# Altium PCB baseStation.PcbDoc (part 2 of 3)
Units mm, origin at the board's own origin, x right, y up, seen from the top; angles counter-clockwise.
Board outline 130 x 90 mm, 4 copper layers (Top Layer, Ground Layer, Power Layer, Bottom Layer), stack 1.574 mm thick; 252 components, 154 nets, 772 pads, 1223 vias.
Unrouted connection lines stored in the file: 134.
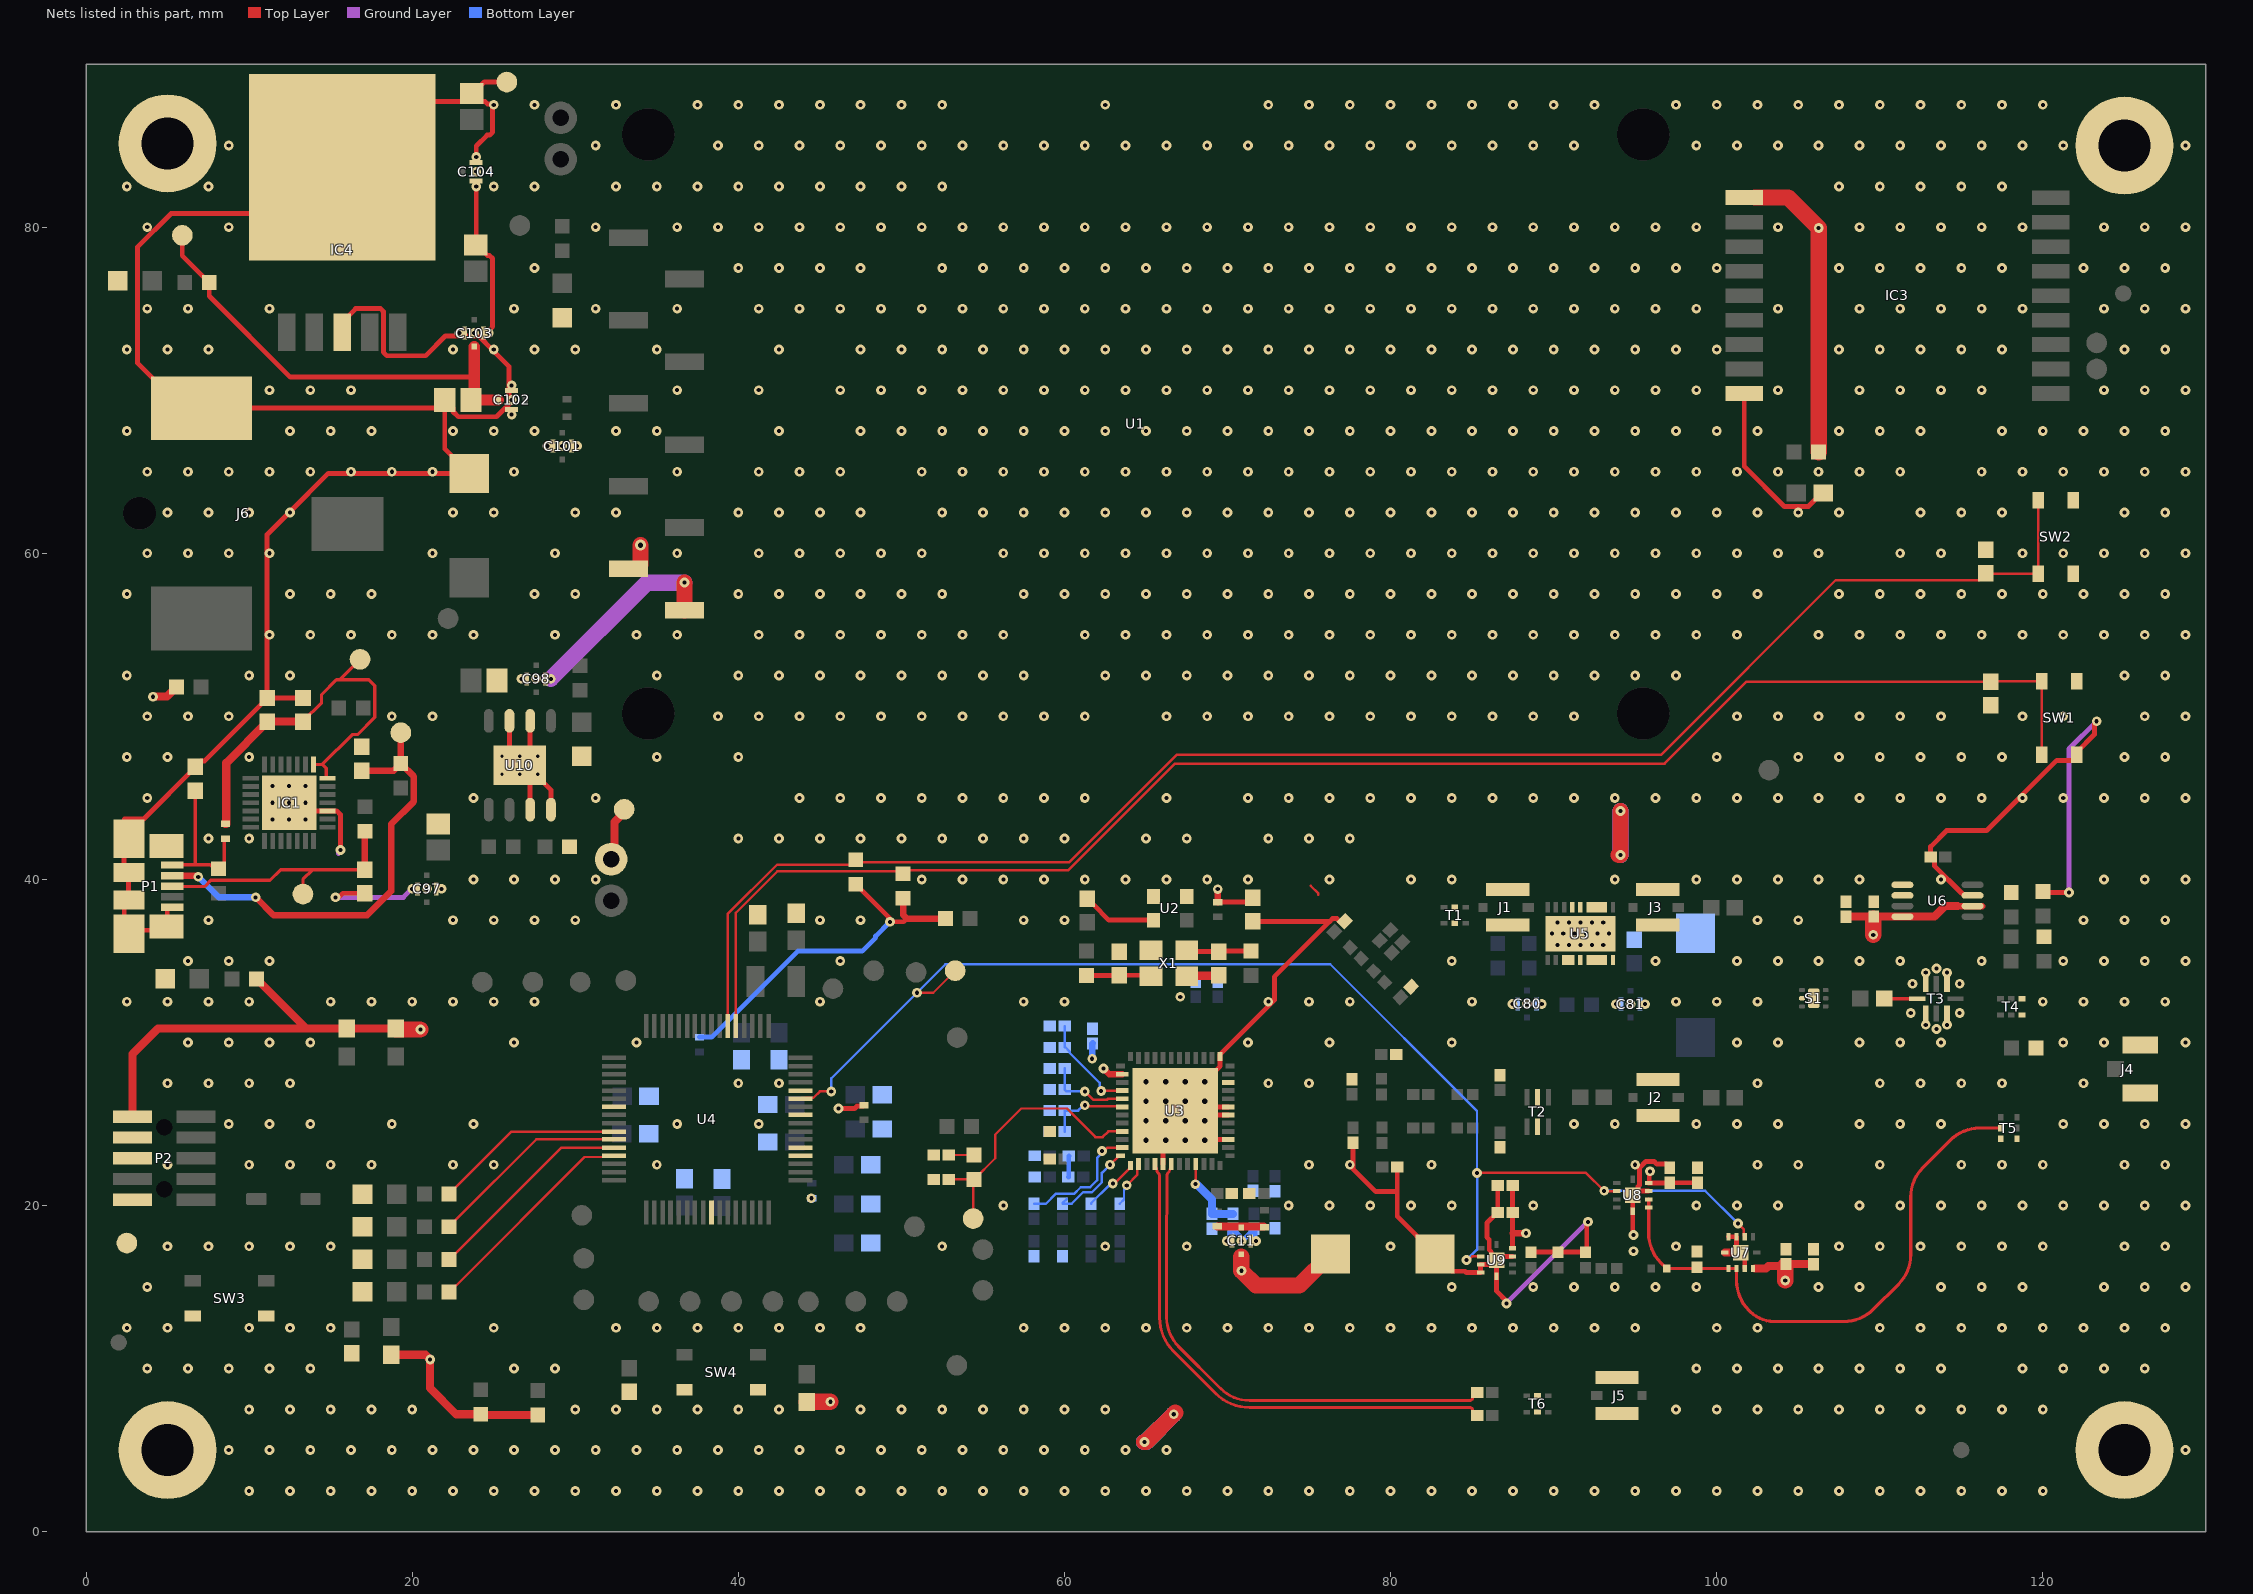
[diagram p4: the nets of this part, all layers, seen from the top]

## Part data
C1 C2 C3 C4 C5 C6 C7 C62 C63 C64 C65 C66 C67 C68 C69 C70 C71 C72 C73 C74 C75 C78 C79: "Capacitor"
C8 C9 C10 C12 C13 C14 C18 C43 C47 C49 C58 C60: library part Cap, "type : free, 0603, 20%"
C11 C80 C81 C97 C101 C102 C103 C104: library part NFM18PS474R0J3D_1, "CAP FEEDTHRU 0.47UF 6.3V 0603", Capacitance=0.47µF, Current=2A, DC Resistance (DCR) (Max)="30 mOhm", ESR (Equivalent Series Resistance)="70 mOhm", Lifetime @ Temp.="1000 Hrs @ 105°C", Manufacturer="Murata Electronics North America", Manufacturer Part Number=NFM18PS474R0J3D, Operating Temperature="-55°C ~ 125°C", Package / Case="0603 (1608 Metric), 3 PC Pad", Ratings=-, Ripple Current - High Frequency="1A @ 100kHz", Supplier Part Number 1=490-6975-1-ND, Tolerance=±20%, Voltage - Rated=6.3V
C15 C82 C105: library part ECASD41C106M060K00, "CAP POLYMER 10UF 20% 16V SMD", Capacitance=10µF, ESR (Equivalent Series Resistance)="60 mOhm @ 100kHz", Lifetime @ Temp.="1000 Hrs @ 105°C", Manufacturer=Murata, Operating Temperature="-40°C ~ 105°C", Package / Case="2917 (7343 Metric)", Ripple Current=1A, Standard Package=3,000, Supplier Part Number 1=490-5482-1-ND, Tolerance=±20%, Voltage Rating=16V
C16 C17 C19 C20 C21 C22 C23 C24 C25 C26 C27 C28 C29 C30 C31 C32 C33 C34 C35 C36 C37 C38 C39 C40 C41 C42 C44 C45 C46 C48 C50 C51 C52 C53 C54 C55 C56 C57 C59 C61 C83 C84 C85 C86 C87 C88 C89 C90 C91 C92 C93 C94 C95 C96: "type : free, 0603, 20%"
C98: library part NFM18PS474R0J3D, "CAP FEEDTHRU 0.47UF 6.3V 0603", Capacitance=0.47µF, Current=2A, DC Resistance (DCR) (Max)="30 mOhm", ESR (Equivalent Series Resistance)="70 mOhm", Lifetime @ Temp.="1000 Hrs @ 105°C", Manufacturer="Murata Electronics North America", Operating Temperature="-55°C ~ 125°C", Package / Case="0603 (1608 Metric), 3 PC Pad", Ratings=-, Ripple Current - High Frequency="1A @ 100kHz", Supplier Part Number 1=490-6975-1-ND, Tolerance=±20%, Voltage - Rated=6.3V
C99 C100 C106 C107 C108: "ceramic"
D1 D2 D3 D4 D6 D7 D8 D9: library part LED
D5: library part BAT54W-HG3-08, "Schottky Diodes & Rectifiers 30V Zener SKY DIODE SOD-123", Package=None
FB1 FB2 FB4 FB5 FB6 FB7: library part BLM15HG102SN1D, "FERRITE BEAD 1 KOHM 0402 1LN", Current Rating (Max)=250mA, DC Resistance (DCR) (Max)="1.1 Ohm", Impedance @ Frequency="1 kOhm @ 100MHz", Manufacturer="Murata Electronics North America", Operating Temperature="-55°C ~ 125°C", Package / Case="0402 (1005 Metric)", Ratings=-, Supplier Part Number 1=490-3999-1-ND
FB3 FB8: library part BLM15PX331SN1D, "FERRITE BEAD 330 OHM 0402 1LN", Current Rating (Max)=1.2A, DC Resistance (DCR) (Max)="150 mOhm", Manufacturer="Murata Electronics North America", Operating Temperature="-55°C ~ 125°C", Package / Case="0402 (1005 Metric)", Ratings=-, Supplier Part Number 1=490-11022-1-ND
FD1 FD2 FD3: library part CMP-00028-00005-1, "Fiducial - Round 1x2mm"
IC1: "Integrated Circuit", Manufacturer_Name="Silicon Labs", Mouser Part Number=634-CP2101-GMR
IC3: "Integrated Circuit", Manufacturer_Name="Espressif Systems", Mouser Part Number=356-ESP32C3WROOM02N4
IC4: "Integrated Circuit", Manufacturer_Name="Analog Devices", Mouser Part Number=584-LT1529CQ-5#PBF
J1 J2 J3 J5: library part MS-156HF, "CONN COAX JACK STR 50 OHM SMD", Dielectric Material="Polyamide (PA), Nylon 6T", Frequency="700MHz ~ 1GHz", Frequency - Max=6GHz, Housing Color=Gold, Manufacturer="Hirose Electric Co Ltd", Manufacturer 2=Anaren, Manufacturer Part Number=MS-156HF(01), Manufacturer Part Number 2=DC0710J5010AHF, Operating Temperature="-40°C ~ 85°C", Package / Case="0805 (2012 Metric)", Power - Max=2W, Supplier Device Package=0805, Supplier Part Number 1=H11669-ND, Voltage Rating=-
J4: library part CMP-0168-00038-1, "SMA Female Edge Multi-Mount Connector for 0.031\" Thick Board"
J6: library part PJ-036BH-SMT-TR, "2.5 x 6.3 mm, 5.0 A, Horizontal, Surface Mount _SMT_, Dc Power Jack Connector", Package=None, Supplier Part Number 1=490-PJ-036BH-SMT-TR
P1: "USB - micro B USB 2.0 Receptacle Connector 5 Position Surface Mount, Right Angle", Package=None
P2: library part CMP-2000-05523-1, "Male Header, Pitch 1.27 mm, 2 x 5 Position, Height 4.55 mm, -40 to 85 degC, RoHS, Tape and Reel", Contact resistance Max=30MOhm, Current Rating=1A, Manufacturer=FCI, Package Description="10-Leads Header, Body 3.43 x 6.35, Pitch 1.27 mm", Package Reference=20021121, Package Version="Rev. J, 03/2013", Supplier Part Number 1=649-202112100010C4LF, Voltage Rating=125V
PTH1 PTH2 PTH3 PTH4: "M3 mounting hole"
R1 R2 R3 R4 R5 R6 R7 R8 R9 R10 R11 R12 R13 R14 R15 R16 R17 R18 R19 R20 R21 R22 R34 R35 R36 R37 R38 R39 R40: library part Res2, "Resistor"
R23 R24 R25 R26 R27 R28 R29 R30 R31 R32 R33: "Resistor"
S1: library part SKY13431-374LF, "IC SWITCH SP2T", Frequency - Lower=500MHz, Insertion Loss @ Frequency="0.8dB @ 5.8GHz", Isolation @ Frequency="20dB @ 5.8GHz (typ)", Manufacturer="Skyworks Solutions Inc.", Operating Temperature="-40°C ~ 85°C", Package / Case="6-XFDFN Exposed Pad", Supplier Device Package="6-DFN (1.5x1.5)", Supplier Part Number 1=863-1651-1-ND, Voltage - Supply="2.5 V ~ 5 V"
SW1 SW2 SW3 SW4: library part CMP-2000-05602-2, "Swicth, SPST, 24 V, -35 to 85 degC, 4-Pin SMD, RoHS, Tape and Reel", Case\/Package=SMD/SMT, Contact Current Rating=50mA, Contact Resistance=100mOhm, Manufacturer="TE Connectivity", Max Operating Temperature=85degC, Max Voltage Rating (DC)=12V, Min Operating Temperature=-35degC, Operating Force=1.57N, Package Description="4-Pin Surface Mount Device, Body 6 x 6 mm, Pitch 4.5 mm", Package Quantity=750, Voltage Rating=24V
T1 T6: library part BD0810J50100AHF, "XFRMR BALUN RF 800-1000MHZ 0805", Frequency Range="800MHz ~ 1GHz", Manufacturer=Anaren, Package / Case="0805 (2012 Metric)", Supplier Part Number 1=1173-1056-2-ND
T2: library part "1:1 BALUN 900MHZ - 0900BL15C050", "1:1 BALUN- 900MHZ 50/50 Ohm", Frequency Range="800 ~ 1000MHz", Manufacturer="Johanson Technology Inc", Manufacturer Part Number=0900BL15C050E, Package / Case="0805 (2012 Metric)", Supplier Part Number 1=712-1022-1-ND
T3: library part 0900LP15B0063, "FILTER LOWPASS 863-960MHZ", Manufacturer="Johanson Technology Inc.", Manufacturer Part Number=0900LP15B0063E, Supplier Part Number 1=712-1635-1-ND
T4: library part DC0710J5020AHF, "COUPLER 20DB 700-1000MHZ 0805", Case Code (Imperial)=0805, Case Code (Metric)=2012, Frequency=700MHz, Manufacturer=Anaren, Max Operating Temperature=85°C, Max Power Dissipation=2W, Min Operating Temperature=-55°C, Package Quantity=4000, Supplier Part Number 1=1173-1085-1-ND
T5: library part DC0710J5010AHF, "Directional Coupler", Frequency="700MHz ~ 1GHz", Manufacturer=Anaren, Package / Case="0805 (2012 Metric)", Power - Max=2W, Supplier Device Package=0805, Supplier Part Number 1=1173-1084-1-ND
TP1 TP2 TP3 TP4 TP5 TP6 TP7 TP8 TP9 TP10 TP11 TP12 TP13 TP14 TP15 TP16 TP17 TP18 TP19 TP20 TP21 TP22 TP23 TP24 TP25 TP26 TP27 TP28 TP29 TP30 TP31 TP32 TP33 TP34 TP35 TP36: library part TestPoint
U1: library part Adafruit_1480, "LCD Module Adafruit 1480, SPI 320x240p 2.2\""
U2: library part 7Q-20.000MCN-T, "OSC TCXO 20.000MHZ CLPD SNWV SMD", Current - Supply (Disable) (Max)=-, Current - Supply (Max)=2mA, Frequency Stability=±500ppb, Manufacturer=Taitien, Manufacturer Part Number=TXEAADSANF-20.000000, Operating Temperature="-30°C ~ 85°C", Package / Case="4-SMD, No Lead", Supplier Part Number 1=1664-1240-1-ND, Voltage - Supply="2.8 V ~ 3.3 V"
U3: "UHF EPC CLASS1 GEN2 READER", Frequency="860MHz ~ 960MHz", Manufacturer="ST Microelectronics", Manufacturer Part Number=AS3993-BQFT, Operating Temperature=-, Package / Case="48-VFQFN Exposed Pad", Supplier Device Package="48-QFN (7x7)", Supplier Part Number 1=AS3993-BQFTTR-ND, Voltage - Supply="2.7 V ~ 3.6 V"
U5: library part TQP9107, "699 – 960 MHz 2-stage Power Amplifier", Manufacturer=Qorvo, Supplier Part Number 1=772-TQP9107
U6: library part MAX4003EUA+T, "IC LOG AMP RF DETECT 45DB 8-MSOP", Frequency="100MHz ~ 2.5GHz", Manufacturer="Maxim Integrated", Package / Case="8-TSSOP, 8-MSOP (0.118\", 3.00mm Width)", Supplier Device Package=8-uMAX, Supplier Part Number 1=MAX4003EUA+TCT-ND, Voltage - Supply="2.7 V ~ 5 V"
U7 U8 U9: library part PE64906MLAA-Z, "IC RF DTC 100-3000MHZ 10QFN", Frequency="100MHz ~ 3GHz", Frequency - Lower=500MHz, Insertion Loss @ Frequency="0.8dB @ 5.8GHz", Isolation @ Frequency="20dB @ 5.8GHz (typ)", Manufacturer="Peregrine Semiconductor", Operating Temperature="-40°C ~ 85°C", Package / Case="10-UFQFN Exposed Pad", Supplier Device Package="10-QFN (2x2)", Supplier Part Number 1=1046-1079-1-ND, Voltage - Supply="2.5 V ~ 5 V"
U10: library part BD00IC0MEFJ-ME2, "Régulateurs de tension LDO IC Pwr Linear Reg Single Output LDO"
W1 W2: library part Jumper, "Jumper Wire"
X1: library part NX3225SA-20.000000MHZ-B2, "CRYSTAL 20.0000MHZ 7.2PF SMD", ESR (Equivalent Series Resistance)="80 Ohm", Frequency=20MHz, Frequency Stability=±15ppm, Frequency Tolerance=±10ppm, Load Capacitance=7.2pF, Manufacturer=NDK, Operating Mode=Fundamental, Operating Temperature="-30°C ~ 85°C", Package / Case="4-SMD, No Lead", Ratings=-, Supplier Part Number 1=644-1098-1-ND
Y1: library part CMP-40224-000019-1, "CRYSTAL 32.768KHZ 12.5PF SMD", Case/Package=SMD/SMT, ESR (Equivalent Series Resistance)=80kR, Frequency=32.768kHz, Frequency Tolerance=10ppm, Load Capacitance=12.5pF, Max Operating Temperature=125°C, Min Operating Temperature=-40°C, Ratings=AEC-Q200, Supplier Part Number 1=520-.327-12.5-34QCST

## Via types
v1: diameter 0.6, hole 0.25, Top Layer to Bottom Layer, tented both sides, 1129 vias
v2: diameter 0.6, hole 0.25, Top Layer to Bottom Layer, 71 vias
v3: diameter 0.66, hole 0.33, Top Layer to Bottom Layer, 17 vias
v4: diameter 0.5, hole 0.2, Top Layer to Bottom Layer, 6 vias

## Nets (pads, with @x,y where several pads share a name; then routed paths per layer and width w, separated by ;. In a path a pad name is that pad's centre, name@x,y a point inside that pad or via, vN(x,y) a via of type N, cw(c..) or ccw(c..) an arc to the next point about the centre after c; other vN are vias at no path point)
3V3: C11.1 C14.1 C15.1 C18.1 C87.2 C88.2 C91.1 C92.1 C93.1 C94.1 C95.1 C96.1 FB2.1 FB5.1 FB6.1 FB7.2 IC3.1 P2.1 R5.2 R6.2 R10.1 R12.2 R13.1 R14.1 R19.2 R20.2 R21.2 R22.2 R36.2 R38.2 TP34.1 U1.2 U3.38 U6.2 U6.8 U7.4 U8.4 U9.4 W1.2 | length 125.5
  Top Layer w0.3: v2(46.143,25.947) 47.126,25.947 47.283,26.104 47.65,26.104 FB7.2@47.7,26.154 ; R6.2@47.298,39.601 49.243,37.656 49.243,37.457 v1(49.3,37.4) 50.134,37.4 50.334,37.6 ; FB2.1@69.4,38.604 71.278,38.604 C14.1@71.55,38.876 ; U9.4@87.474,17.461 87.48,17.467 87.48,18.3 87.48,19.556 C94.1@87.486,19.561 C92.1@87.486,21.241 ; v1(95.9,22.1) 95.862,22.062 95.862,21.405 U8.4@95.845,21.387 ; C95.1@98.81,21.394 C96.1@97.12,21.394 97.113,21.387 U8.4@95.845,21.387 ; C93.1@104.25,16.414 C93.1@104.255,16.409 ; C91.1@105.935,16.409 C91.1@105.94,16.404 ; C88.2@107.92,37.714 cw(c107.944,37.69) C88.2@107.944,37.724 ; C87.2@109.63,37.724 109.635,37.72 C87.2@109.639,37.715 ; U6.8@111.385,37.72 U6.8@111.39,37.715 ; U8.4@95.845,21.387 95.837,21.38 U8.4@95.825,21.38 95.832,21.387 U8.4@95.845,21.387
  Top Layer w0.4: R5.2@50.1,38.849 50.1,37.834 50.334,37.6 R10.1@52.698,37.6 ; v1(62.4,28.4) 62.75,28.05 U3.38@63.55,28.05 ; FB2.1@69.4,38.604 v1(69.4,39.4) ; 87.48,18.3 v1(88.3,18.3) ; 114.766,38.365 U6.2@116.293,38.365
  Top Layer w0.5: P2.1@2.85,25.44 2.85,29.3 4.401,30.851 R19.2@15.744,30.851 ; v1(4.1,51.2) 4.119,51.219 4.968,51.219 R38.2@5.343,51.594 ; R38.2@5.344,51.594 R38.2@5.549,51.799 ; R36.2@10.451,33.9 R36.2@10.656,33.695 ; R36.2@10.656,33.694 13.449,30.901 ; R19.2@15.794,30.851 R19.2@16,30.851 R20.2@19,30.851 ; R21.2@18.7,10.849 20.807,10.849 v1(21.1,10.556) 21.1,8.8 22.702,7.198 R13.1@24.2,7.198 24.249,7.149 R14.1@27.7,7.149 ; W1.2@32.2,41.24 32.4,41.44 32.4,43.522 33,44.122 TP34.1@33,44.3 ; U1.2@33.27,59.04 33.74,59.04 U1.2@34,59.3 ; 102.354,16.135 103.015,16.135 103.164,16.284 104.164,16.284 104.25,16.37 C93.1@104.25,16.414 ; C93.1@104.255,16.409 C91.1@105.935,16.409 ; C88.2@107.944,37.724 C87.2@109.63,37.724 ; C87.2@109.635,37.72 U6.8@111.385,37.72 ; U6.8@111.39,37.715 113.355,37.715 114.005,38.365 114.766,38.365
  Top Layer w1: R20.2@19,30.851 19,30.806 19.006,30.8 v1(20.5,30.8) ; U1.2@34,59.3 v3(34,60.5) ; R22.2@44.2,7.949 44.2,7.959 44.206,7.965 v1(45.64,7.965) ; C11.1@70.85,16.853 v1(70.85,16.002) 71.752,15.1 ; 72.6,15.1 71.752,15.1 ; C15.1@76.32,17.02 74.4,15.1 71.752,15.1 ; IC3.1@102.329,81.823 104.377,81.823 v1(106.251,79.949) R12.2@106.251,66.2 ; v1(104.2,15.4) C93.1@104.2,16.295 ; v1(109.6,36.6) C87.2@109.6,37.605
  Bottom Layer w0.3: FB5.1@37.63,30.324 38.367,30.324 43.643,35.6 47.6,35.6 48.421,36.421 48.421,36.521 v1(49.3,37.4)
  Bottom Layer w0.4: v1(61.7,29) 61.715,29.015 61.715,29.924 C18.1@61.73,29.939
  Bottom Layer w0.5: v1(44.475,20.446) FB6.1@44.5,20.446 44.5,20.409 FB6.1@44.488,20.396
6V: C102.3 C103.1 C106.2 R39.2 TP35.1 | length 27.7
  Top Layer w0.3: TP35.1@5.9,79.5 5.9,78.252 7.551,76.601 7.551,75.778 12.529,70.8 23.8,70.8
  Top Layer w0.7: C103.1@23.8,72.675 23.8,70.8 23.8,69.6 C106.2@23.6,69.4 C102.3@25.275,69.4
ADG: C28.1 C29.1 U3.42 | length 5
  Top Layer w0.15: v1(61.25,26.15) 61.3,26.1 63.5,26.1 U3.42@63.55,26.05
  Bottom Layer w0.15: C28.1@60.011,24.528 C29.1@60.011,25.822 60.835,25.822 61.163,26.15 v1(61.25,26.15)
CBIB: C48.1 C49.1 U3.9 | length 4.8
  Top Layer w0.15: v1(68.025,21.31) 68.037,21.322 68.037,22.537 U3.9@68.05,22.55
  Bottom Layer w0.3: v1(68.025,21.31) v1@68.1,21.31
  Bottom Layer w0.5: v1@68.1,21.31 69.05,20.36 C49.1@69.05,19.53 ; C49.1@69.05,19.486 C48.1@70.34,19.486
CCC: C90.2 L7.1 T5.2 U7.1 U7.2 U8.1 U8.2 | length 35.1
  Top Layer w0.199: U8.2@95.825,20.38 U8.1@95.825,19.88 95.825,18.292 ccw(c98.365,18.292) 96.569,16.496 C90.2@96.925,16.14 101.215,16.14 U7.2@101.22,16.135 101.22,15.939 101.22,15.382 ccw(c103.76,15.382) 101.964,13.586 102.06,13.49 ccw(c103.509,14.939) 103.509,12.89 105.328,12.89 107.808,12.89 ccw(c107.808,15.43) 109.604,13.634 111.156,15.186 ccw(c109.36,16.982) 111.9,16.982 111.9,20.528 cw(c114.44,20.528) 112.644,22.324 114.326,24.006 cw(c116.122,22.21) 116.122,24.75 T5.2@117.425,24.75
CD1: C24.1 C25.1 U3.41 | length 5.1
  Top Layer w0.15: v1(61.25,27) 61.75,26.5 62.616,26.5 62.666,26.55 U3.41@63.55,26.55
  Bottom Layer w0.15: C25.1@60.011,28.411 C24.1@60.011,27.117 60.128,27 v1(61.25,27)
CD2: C26.1 C27.1 U3.40 | length 6.2
  Top Layer w0.15: v1(62.25,27.025) 62.262,27.037 63.537,27.037 U3.40@63.55,27.05
  Bottom Layer w0.15: C26.1@60.011,31 C27.1@60.011,29.706 60.056,29.706 60.317,29.444 60.317,29.373 62.167,27.523 62.167,27.108 v1(62.25,27.025)
COMN_A: C54.1 U3.48 | length 5.5
  Top Layer w0.15: v1(62.8,22.5) 63.25,22.95 63.25,22.975 63.325,23.05 U3.48@63.45,23.05
  Bottom Layer w0.15: C54.1@60.151,20.411 59.89,20.15 C54.1@59.89,20.106 60.435,20.106 61.143,20.814 61.689,20.814 62.3,21.425 62.3,22 v1(62.8,22.5)
COMN_B: C56.1 U3.2 | length 2.9
  Top Layer w0.15: v1(63.82,21.24) 64.475,21.895 64.475,22.475 U3.2@64.55,22.55
  Bottom Layer w0.15: C56.1@63.39,20.106 63.651,20.367 63.651,20.949 63.82,21.118 v1(63.82,21.24)
COMP_A: C53.1 U3.47 | length 7.7
  Top Layer w0.15: v1(62.3,23.34) 62.422,23.34 62.632,23.55 U3.47@63.55,23.55
  Bottom Layer w0.15: C53.1@58.14,20.1 58.849,20.1 59.461,20.711 60.591,20.711 61,21.12 61.571,21.12 62,21.549 62,22.918 62.3,23.218 v1(62.3,23.34)
COMP_B: C55.1 U3.1 | length 3.5
  Top Layer w0.15: v1(62.964,21.346) 63.071,21.346 64.05,22.325 U3.1@64.05,22.45
  Bottom Layer w0.15: C55.1@61.64,20.106 61.64,20.15 62.75,21.26 62.878,21.26 v1(62.964,21.346)
FC7_MISO: U4.28
GND: C1.1 C2.1 C3.1 C4.1 C5.1 C6.1 C7.1 C9.2 C10.2 C11.2 C12.2 C13.2 C14.2 C15.2 C16.2 C17.2 C18.2 C19.2 C21.2 C23.2 C24.2 C25.2 C26.2 C27.2 C28.2 C29.2 C31.2 C32.1 C33.2 C34.2 C35.2 C36.2 C37.2 C38.2 C40.2 C42.2 C43.2 C44.2 C45.2 C46.2 C47.2 C48.2 C49.2 C50.2 C51.1 C57.2 C58.2 C62.1 C63.1 C64.1 C65.1 C66.1 C67.1 C68.1 C69.1 C70.1 C71.1 C72.1 C73.1 C74.1 C75.1 C76.1 C77.2 C78.1 C79.1 C80.2 C81.2 C82.2 C83.1 C87.1 C88.1 C89.1 C91.2 C92.2 C93.2 C94.2 C95.2 C96.2 C97.2 C98.2 C99.1 C100.1 C101.2 C102.2 C103.2 C104.2 C105.2 C106.1 C107.1 C108.1 D1.K D2.K D3.K D4.K D6.K D7.K D8.K D9.K IC1.3 IC1.29 IC3.9 IC4.3 IC4.6 J1.G1 J1.G2 J2.G1 J2.G2 J3.G1 J3.G2 J4.2 J4.3 J5.G1 J5.G2 J6.2 L7.2 L8.2 P1.5 P1.SH1 P1.SH2 P1.SH3 P1.SH4 P1.SH5 P1.SH6 P2.3 P2.5 P2.9 PTH1.1 PTH2.1 PTH3.1 PTH4.1 R27.2 R28.2 R29.2 R30.2 R32.2 R33.2 R37.1 S1.5 S1.7 SW1.3 SW1.4 SW2.3 SW2.4 SW3.3 SW3.4 SW4.3 SW4.4 T1.2 T1.5 T2.2 T2.5 T3.1 T3.3 T3.5 T3.7 T4.3 T4.4 T5.3 T5.4 T6.2 T6.5 TP23.1 TP32.1 U1.1 U2.1 U2.2 U3.5 U3.15 U3.18 U3.19 U3.22 U3.25 U3.49 U4.9 U4.20 U4.21 U4.25 U4.55 U5.3 U5.4 U5.5 U5.6 U5.8 U5.9 U5.10 U5.14 U6.3 U6.5 U6.6 U7.3 U7.8 U7.9 U7.10 U8.3 U8.10 U9.3 U9.8 U9.9 U9.10 U10.3 U10.4 U10.6 U10.7 U10.9 X1.2 X1.4 | length 349.3
  Top Layer w0.15: 75.1,39.6 75.574,39.126 75.574,39.05
  Top Layer w0.3: P1.SH4@2.317,40.42 2.613,40.124 2.613,39.041 2.317,38.745 2.34,38.723 2.34,36.693 P1.SH6@2.317,36.67 ; P1.SH3@2.34,42.518 2.34,43.7 3.524,43.7 6.7,46.876 6.7,46.924 7.029,47.253 7.252,47.253 11.1,51.102 C4.1@11.1,51.126 ; P1.SH4@2.636,40.42 2.317,40.739 2.317,42.177 P1.SH3@2.636,42.495 ; P1.SH2@4.617,37.12 4.38,36.883 P1.SH6@2.53,36.883 ; P1.SH2@4.74,37.12 4.977,37.357 P1.5@4.977,38.283 ; IC1.29@11.36,45.716 11.36,44.7 11.36,43.684 12.376,43.684 13.392,43.684 IC1.29@13.392,44.2 ; IC1.29@12.376,45.716 12.376,44.7 IC1.29@13.392,44.7 ; C5.1@13.3,51.126 C4.1@11.1,51.126 ; IC1.29@13.392,45.716 IC1.29@13.392,44.7 ; v1(15.3,38.9) 15.489,38.9 15.738,39.148 C3.1@17.1,39.148 ; v1(15.6,41.8) 15.6,43.974 15.374,44.2 IC1.29@13.392,44.2 ; IC4.3@15.7,73.558 15.7,74.167 16.534,75.001 18.06,75.001 18.236,74.825 18.236,72.326 18.446,72.115 20.826,72.115 22.036,73.325 22.9,73.325 C103.2@23.225,73.325 ; v1(23.8,73.5) 23.8,73.325 C103.2@23.225,73.325 ; v1@23.825,73.325 24.069,73.325 24.947,72.447 25.925,71.469 25.925,70.3 25.925,69.975 25.925,69.4 25.925,69.131 25.166,68.372 22.823,68.372 22.501,68.695 22.501,68.898 C106.1@21.998,69.4 ; v1(23.925,82.5) 23.925,78.927 C107.1@23.9,78.902 23.976,78.902 24.625,78.252 24.752,78.252 24.928,78.077 24.928,73.903 24.7,73.675 v1(24.7,73.5) ; v1(23.925,84.3) 23.925,84.975 24.597,85.647 24.752,85.647 24.928,85.823 24.928,87.376 24.752,87.552 24.625,87.552 24.478,87.698 24.155,87.698 C108.1@23.653,88.201 ; TP32.1@25.8,88.9 24.428,88.9 23.728,88.201 C108.1@23.653,88.201 ; U10.7@25.965,49.725 25.965,47.635 U10.9@26.6,47 ; U10.3@27.235,44.275 27.235,46.365 U10.9@26.6,47 ; U10.6@27.235,49.725 27.235,47.635 U10.9@26.6,47 ; U10.4@28.505,44.275 28.505,45.495 27,47 U10.9@26.6,47 ; U3.5@66.05,22.55 U3.49@66.05,24 ; v3(67.4,25.2) U3.49@68.55,24.05 ; U3.49@68.6,24.05 U3.15@70.05,24.05 ; U3.49@68.6,25.55 U3.18@70.05,25.55 ; U3.49@68.6,26.05 U3.19@70.05,26.05 ; v3(68.6,27.6) 69.55,28.55 U3.25@69.55,29.15 69.55,29.275 72.871,32.596 72.871,34.019 76.276,37.424 ; C14.2@71.55,37.424 76.276,37.424 ; C19.2@77.161,37.401 76.897,37.401 76.703,37.595 76.446,37.595 76.276,37.424 ; C50.2@77.69,23.854 77.69,22.261 79.099,20.852 80.406,20.852 ; C23.2@80.406,22.37 80.406,20.852 ; C92.2@86.574,21.241 C94.2@86.574,19.561 86.53,19.561 85.9,18.931 85.9,18.059 86.05,17.909 86.05,17.282 86.175,17.157 86.175,16.956 U9.10@86.5,16.631 ; v1(87.1,14) 87.1,14.143 86.5,14.743 U9.10@86.5,15.656 U9.10@86.5,16.631 ; U9.3@87.475,16.881 86.75,16.881 U9.10@86.5,16.631 ; R33.2@88.6,17.14 R32.2@90.28,17.14 L8.2@91.96,17.14 92.03,17.21 92.03,18.93 v1(92.1,19) ; v1(94.9,18.2) 94.85,18.25 U8.10@94.85,19.655 U8.10@94.85,20.63 U8.10@95.1,20.88 ; U8.3@95.825,20.88 U8.10@95.1,20.88 ; C96.2@97.12,22.306 97.12,22.35 96.934,22.536 96.334,22.536 96.17,22.7 95.651,22.7 95.275,22.324 95.275,21.256 95.175,21.156 95.175,20.955 U8.10@95.1,20.88 ; U7.9@100.72,18.085 U7.8@101.22,18.085 101.22,17.36 U7.10@101.47,17.11 101.72,16.86 U7.3@101.72,16.135 ; IC3.9@101.686,69.8 101.686,65.332 104.147,62.871 105.623,62.871 106.452,63.7 C72.1@106.526,63.7 ; U6.3@115.69,39.015 115.188,39.015 115.038,39.165 115.008,39.165 113.345,40.828 113.345,41.194 113.159,41.38 C89.1@113.114,41.38 113.114,42.014 114.1,43 116.549,43 120.849,47.3 121.875,47.3 122.075,47.5 SW1.3@122.075,47.65 122.075,47.8 123.166,48.891 123.166,49.566 v1(123.3,49.7) ; R30.2@120,39.251 120.051,39.2 v1(121.6,39.2) ; P1.SH6@2.317,36.67 P1.SH6@2.53,36.883 ; P1.SH6@2.317,36.67 P1.SH6@2.53,36.883 ; C4.1@11.1,51.126 11.1,55 11.1,60 11.1,61.149 12.475,62.525 14.851,64.9 16.25,64.9 18.75,64.9 21.25,64.9 C105.2@23.5,64.9 21.998,66.402 C106.1@21.998,69.4 ; IC1.29@13.392,44.2 IC1.29@13.392,44.7 ; C106.1@21.998,69.4 21.498,68.9 J6.2@7.075,68.9 5.925,68.9 3.15,71.675 3.15,78.772 5.213,80.835 12.868,80.835 IC4.6@15.7,83.667 19.731,87.698 23.15,87.698 C108.1@23.653,88.201 ; C103.2@23.175,73.325 23,73.5 C103.2@23.175,73.325 ; C103.2@23.175,73.325 C103.2@23.225,73.325 ; 80.406,20.852 80.406,19.334 C15.2@82.72,17.02 83.77,15.97 84.566,15.97 84.654,15.881 U9.9@85.525,15.881 U9.8@85.525,16.381 86.25,16.381 U9.10@86.5,16.631
  Top Layer w0.5: X1.2@67.5,34.05 67.537,34.087 69.413,34.087 C13.2@69.45,34.124 ; U7.10@100.516,17.11 U7.10@101.47,17.11
  Top Layer w1: U1.1@36.7,56.5 v1(36.7,58.2) ; v1(64.9,5.5) 65,5.5 v2@66.8,7.3 ; v2(94.1,41.5) 94,41.5 94.1,41.6 v2(94.1,44.2)
  Ground Layer w0.3: v1(15.3,38.9) 19.461,38.9 19.983,39.422 v1(20,39.422) ; v1@15.476,41.6 15.476,41.676 v1(15.6,41.8) ; v3(65,24) v3(65,25.2) v3(66.2,25.2) v3(66.2,26.4) ; v3(65,26.4) v3(66.2,26.4) ; v3(65,27.6) v3(66.2,26.4) ; v3(66.2,24) v3(67.4,24) v3(67.4,25.2) v3(67.4,26.4) ; v3(66.2,27.6) v3(67.4,27.6) v3(67.4,26.4) ; v3(68.6,25.2) v3(68.6,26.4) v3(67.4,26.4) ; v3(68.6,27.6) v3(67.4,26.4) ; v1(87.1,14) v1(92.1,19) ; v1(121.6,39.2) 121.6,48 v1(123.3,49.7) ; v3(66.2,26.4) v3(67.4,26.4)
  Ground Layer w1: v1(28.5,52.3) 34.4,58.2 v1(36.7,58.2) ; v1(64.9,5.5) 65,5.5 v2(66.7,7.2) ; v2(94.1,41.5) v2(94.1,44.2)
  Bottom Layer w0.3: C35.2@60.244,21.74 60.259,21.755 60.259,23.015 C36.2@60.274,23.03 ; v1(69.95,17.83) 69.95,17.911 70.154,18.115 70.154,18.388 C48.2@70.34,18.574 70.34,18.53 70.793,18.077 70.793,17.887 v1(70.85,17.83) 70.92,17.83 71.62,18.53 C47.2@71.62,18.574 71.693,18.502 71.693,17.887 v1(71.75,17.83)
  Bottom Layer w1: v1(64.9,5.5) 65,5.5 v2(66.7,7.2) ; v2(94.1,41.5) v2(94.1,44.2)
  other v1: 10,2.5 12.5,2.5 15,2.5 17.5,2.5 20,2.5 22.5,2.5 25,2.5 27.5,2.5 30,2.5 32.5,2.5 35,2.5 37.5,2.5 40,2.5 42.5,2.5 45,2.5 47.5,2.5 50,2.5 52.5,2.5 55,2.5 57.5,2.5 60,2.5 62.5,2.5 65,2.5 67.5,2.5 70,2.5 72.5,2.5 75,2.5 77.5,2.5 80,2.5 82.5,2.5 85,2.5 87.5,2.5 90,2.5 92.5,2.5 95,2.5 97.5,2.5 100,2.5 102.5,2.5 105,2.5 107.5,2.5 110,2.5 112.5,2.5 115,2.5 117.5,2.5 120,2.5 8.75,5 11.25,5 13.75,5 16.25,5 18.75,5 21.25,5 23.75,5 26.25,5 28.75,5 31.25,5 33.75,5 36.25,5 38.75,5 41.25,5 43.75,5 46.25,5 48.75,5 51.25,5 53.75,5 56.25,5 58.75,5 61.25,5 63.75,5 66.25,5 128.75,5 10,7.5 12.5,7.5 15,7.5 17.5,7.5 20,7.5 30,7.5 32.5,7.5 35,7.5 37.5,7.5 40,7.5 42.5,7.5 47.5,7.5 50,7.5 52.5,7.5 55,7.5 57.5,7.5 60,7.5 62.5,7.5 97.5,7.5 100,7.5 102.5,7.5 105,7.5 107.5,7.5 110,7.5 112.5,7.5 115,7.5 117.5,7.5 120,7.5 3.75,10 6.25,10 8.75,10 11.25,10 13.75,10 26.25,10 28.75,10 98.75,10 101.25,10 103.75,10 106.25,10 108.75,10 111.25,10 113.75,10 118.75,10 121.25,10 123.75,10 126.25,10 2.5,12.5 5,12.5 10,12.5 12.5,12.5 15,12.5 25,12.5 32.5,12.5 35,12.5 37.5,12.5 40,12.5 42.5,12.5 45,12.5 47.5,12.5 57.5,12.5 60,12.5 62.5,12.5 65,12.5 67.5,12.5 70,12.5 72.5,12.5 75,12.5 77.5,12.5 80,12.5 82.5,12.5 85,12.5 87.5,12.5 90,12.5 92.5,12.5 95,12.5 100,12.5 102.5,12.5 110,12.5 112.5,12.5 115,12.5 117.5,12.5 120,12.5 122.5,12.5 125,12.5 127.5,12.5 3.75,15 83.75,15 88.75,15 91.25,15 93.75,15 96.25,15 98.75,15 106.25,15 108.75,15 113.75,15 116.25,15 118.75,15 123.75,15 126.25,15 128.75,15 94.9,17.2 5,17.5 7.5,17.5 10,17.5 12.5,17.5 15,17.5 52.5,17.5 62.5,17.5 67.5,17.5 80,17.5 97.5,17.5 107.5,17.5 110,17.5 112.5,17.5 115,17.5 117.5,17.5 120,17.5 125,17.5 127.5,17.5 56.25,20 73.75,20 76.25,20 78.75,20 81.25,20 83.75,20 88.75,20 98.75,20 101.25,20 103.75,20 108.75,20 111.25,20 113.75,20 116.25,20 118.75,20 121.25,20 123.75,20 126.25,20 128.75,20 5,22.5 10,22.5 12.5,22.5 15,22.5 17.5,22.5 22.5,22.5 25,22.5 35,22.5 75,22.5 77.5,22.5 82.5,22.5 95,22.5 102.5,22.5 105,22.5 110,22.5 115,22.5 117.5,22.5 120,22.5 125,22.5 127.5,22.5 8.75,25 11.25,25 13.75,25 18.75,25 23.75,25 36.25,25 41.25,25 91.25,25 93.75,25 98.75,25 101.25,25 103.75,25 108.75,25 111.25,25 113.75,25 121.25,25 123.75,25 126.25,25 128.75,25 5,27.5 7.5,27.5 10,27.5 12.5,27.5 40,27.5 42.5,27.5 72.5,27.5 75,27.5 102.5,27.5 110,27.5 112.5,27.5 115,27.5 117.5,27.5 122.5,27.5 6.25,30 8.75,30 11.25,30 13.75,30 26.25,30 33.75,30 71.25,30 76.25,30 83.75,30 101.25,30 103.75,30 108.75,30 111.25,30 113.75,30 121.25,30 123.75,30 128.75,30 111.9,31.8 114.9,31.8 93.81,32.35 94.71,32.35 95.61,32.35 87.47,32.36 88.37,32.36 89.27,32.36 2.5,32.5 5,32.5 7.5,32.5 10,32.5 15,32.5 17.5,32.5 20,32.5 22.5,32.5 25,32.5 27.5,32.5 45,32.5 57.5,32.5 60,32.5 72.5,32.5 75,32.5 77.5,32.5 85,32.5 97.5,32.5 100,32.5 102.5,32.5 120,32.5 122.5,32.5 125,32.5 127.5,32.5 67.1,32.8 112,33.6 114.9,33.6 6.25,35 8.75,35 11.25,35 46.25,35 83.75,35 96.25,35 101.25,35 103.75,35 106.25,35 108.75,35 111.25,35 116.25,35 121.25,35 123.75,35 126.25,35 128.75,35 7.5,37.5 22.5,37.5 25,37.5 27.5,37.5 30,37.5 45,37.5 47.5,37.5 57.5,37.5 60,37.5 102.5,37.5 105,37.5 122.5,37.5 125,37.5 127.5,37.5 20.9,39.422 21.8,39.422 23.75,40 26.25,40 28.75,40 31.25,40 51.25,40 53.75,40 56.25,40 58.75,40 61.25,40 63.75,40 66.25,40 68.75,40 71.25,40 76.25,40 81.25,40 83.75,40 93.75,40 98.75,40 101.25,40 103.75,40 106.25,40 108.75,40 113.75,40 123.75,40 126.25,40 128.75,40 7.5,42.5 10,42.5 40,42.5 42.5,42.5 45,42.5 47.5,42.5 50,42.5 52.5,42.5 55,42.5 57.5,42.5 60,42.5 65,42.5 67.5,42.5 72.5,42.5 75,42.5 77.5,42.5 3.75,45 23.75,45 31.25,45 43.75,45 46.25,45 48.75,45 51.25,45 53.75,45 56.25,45 58.75,45 61.25,45 66.25,45 71.25,45 73.75,45 76.25,45 78.75,45 81.25,45 83.75,45 86.25,45 88.75,45 91.25,45 93.75,45 96.25,45 98.75,45 101.25,45 103.75,45 106.25,45 108.75,45 111.25,45 113.75,45 116.25,45 118.75,45 121.25,45 123.75,45 126.25,45 128.75,45 2.5,47.5 5,47.5 10,47.5 35,47.5 40,47.5 100,47.5 105,47.5 107.5,47.5 110,47.5 112.5,47.5 115,47.5 117.5,47.5 125,47.5 127.5,47.5 3.75,50 6.25,50 8.75,50 18.75,50 21.25,50 38.75,50 41.25,50 43.75,50 46.25,50 48.75,50 51.25,50 53.75,50 56.25,50 58.75,50 61.25,50 66.25,50 68.75,50 71.25,50 73.75,50 76.25,50 78.75,50 81.25,50 83.75,50 86.25,50 88.75,50 91.25,50 101.25,50 103.75,50 106.25,50 108.75,50 111.25,50 113.75,50 118.75,50 121.25,50 126.25,50 128.75,50 26.7,52.3 27.6,52.3 2.5,52.5 10,52.5 12.5,52.5 35,52.5 40,52.5 42.5,52.5 45,52.5 47.5,52.5 50,52.5 52.5,52.5 55,52.5 57.5,52.5 62.5,52.5 65,52.5 67.5,52.5 70,52.5 72.5,52.5 75,52.5 77.5,52.5 80,52.5 82.5,52.5 85,52.5 87.5,52.5 90,52.5 92.5,52.5 95,52.5 97.5,52.5 125,52.5 127.5,52.5 11.25,55 13.75,55 16.25,55 18.75,55 21.25,55 23.75,55 28.75,55 33.75,55 36.25,55 41.25,55 43.75,55 46.25,55 48.75,55 51.25,55 53.75,55 56.25,55 61.25,55 63.75,55 66.25,55 68.75,55 71.25,55 73.75,55 76.25,55 78.75,55 81.25,55 83.75,55 86.25,55 88.75,55 91.25,55 93.75,55 96.25,55 98.75,55 101.25,55 106.25,55 108.75,55 111.25,55 113.75,55 116.25,55 118.75,55 121.25,55 123.75,55 126.25,55 128.75,55 2.5,57.5 12.5,57.5 15,57.5 17.5,57.5 27.5,57.5 30,57.5 40,57.5 42.5,57.5 45,57.5 47.5,57.5 50,57.5 52.5,57.5 57.5,57.5 60,57.5 62.5,57.5 65,57.5 67.5,57.5 70,57.5 72.5,57.5 75,57.5 77.5,57.5 80,57.5 82.5,57.5 85,57.5 87.5,57.5 90,57.5 92.5,57.5 95,57.5 97.5,57.5 100,57.5 102.5,57.5 107.5,57.5 110,57.5 112.5,57.5 115,57.5 117.5,57.5 120,57.5 122.5,57.5 125,57.5 127.5,57.5 3.75,60 6.25,60 8.75,60 11.25,60 21.25,60 28.75,60 36.25,60 41.25,60 43.75,60 46.25,60 48.75,60 51.25,60 56.25,60 58.75,60 61.25,60 63.75,60 66.25,60 68.75,60 71.25,60 73.75,60 76.25,60 78.75,60 81.25,60 83.75,60 86.25,60 88.75,60 91.25,60 93.75,60 96.25,60 98.75,60 101.25,60 103.75,60 106.25,60 111.25,60 113.75,60 118.75,60 121.25,60 123.75,60 126.25,60 128.75,60 5,62.5 7.5,62.5 10,62.5 12.5,62.5 22.5,62.5 25,62.5 30,62.5 32.5,62.5 40,62.5 42.5,62.5 45,62.5 47.5,62.5 52.5,62.5 55,62.5 57.5,62.5 60,62.5 62.5,62.5 65,62.5 67.5,62.5 70,62.5 72.5,62.5 75,62.5 77.5,62.5 80,62.5 82.5,62.5 85,62.5 87.5,62.5 90,62.5 92.5,62.5 95,62.5 97.5,62.5 100,62.5 102.5,62.5 105,62.5 107.5,62.5 112.5,62.5 115,62.5 117.5,62.5 125,62.5 127.5,62.5 3.75,65 6.25,65 8.75,65 11.25,65 13.75,65 16.25,65 18.75,65 21.25,65 26.25,65 36.25,65 41.25,65 43.75,65 46.25,65 51.25,65 53.75,65 56.25,65 58.75,65 61.25,65 63.75,65 66.25,65 68.75,65 71.25,65 73.75,65 76.25,65 78.75,65 81.25,65 83.75,65 86.25,65 88.75,65 91.25,65 93.75,65 96.25,65 98.75,65 101.25,65 103.75,65 106.25,65 108.75,65 111.25,65 116.25,65 118.75,65 121.25,65 123.75,65 126.25,65 128.75,65 28.3,66.575 29.2,66.575 30.1,66.575 2.5,67.5 12.5,67.5 15,67.5 17.5,67.5 22.5,67.5 25,67.5 27.5,67.5 32.5,67.5 35,67.5 42.5,67.5 47.5,67.5 50,67.5 52.5,67.5 55,67.5 57.5,67.5 60,67.5 62.5,67.5 65,67.5 67.5,67.5 70,67.5 72.5,67.5 75,67.5 77.5,67.5 80,67.5 82.5,67.5 85,67.5 87.5,67.5 90,67.5 92.5,67.5 95,67.5 97.5,67.5 100,67.5 102.5,67.5 107.5,67.5 110,67.5 112.5,67.5 117.5,67.5 120,67.5 122.5,67.5 125,67.5 127.5,67.5 26.1,68.5 26.1,69.4 11.25,70 13.75,70 16.25,70 36.25,70 41.25,70 46.25,70 48.75,70 51.25,70 53.75,70 56.25,70 58.75,70 61.25,70 63.75,70 66.25,70 68.75,70 71.25,70 73.75,70 76.25,70 78.75,70 81.25,70 83.75,70 86.25,70 88.75,70 91.25,70 93.75,70 96.25,70 98.75,70 103.75,70 108.75,70 111.25,70 113.75,70 116.25,70 123.75,70 126.25,70 128.75,70 26.1,70.3 2.5,72.5 5,72.5 7.5,72.5 22.5,72.5 25,72.5 27.5,72.5 30,72.5 35,72.5 42.5,72.5 47.5,72.5 50,72.5 52.5,72.5 55,72.5 57.5,72.5 60,72.5 62.5,72.5 65,72.5 67.5,72.5 70,72.5 72.5,72.5 75,72.5 77.5,72.5 80,72.5 82.5,72.5 85,72.5 87.5,72.5 90,72.5 92.5,72.5 95,72.5 97.5,72.5 100,72.5 107.5,72.5 110,72.5 112.5,72.5 115,72.5 117.5,72.5 125,72.5 127.5,72.5 22.9,73.5 3.75,75 6.25,75 11.25,75 26.25,75 31.25,75 36.25,75 41.25,75 43.75,75 46.25,75 48.75,75 51.25,75 53.75,75 56.25,75 58.75,75 61.25,75 63.75,75 66.25,75 68.75,75 71.25,75 73.75,75 76.25,75 78.75,75 81.25,75 83.75,75 86.25,75 88.75,75 91.25,75 93.75,75 96.25,75 98.75,75 103.75,75 108.75,75 111.25,75 113.75,75 116.25,75 118.75,75 123.75,75 126.25,75 128.75,75 27.5,77.5 40,77.5 42.5,77.5 45,77.5 47.5,77.5 52.5,77.5 55,77.5 57.5,77.5 60,77.5 62.5,77.5 65,77.5 67.5,77.5 70,77.5 72.5,77.5 75,77.5 77.5,77.5 80,77.5 82.5,77.5 85,77.5 87.5,77.5 90,77.5 92.5,77.5 95,77.5 97.5,77.5 100,77.5 107.5,77.5 110,77.5 112.5,77.5 115,77.5 117.5,77.5 122.5,77.5 125,77.5 127.5,77.5 3.75,80 8.75,80 31.25,80 36.25,80 38.75,80 41.25,80 43.75,80 46.25,80 48.75,80 51.25,80 53.75,80 56.25,80 58.75,80 61.25,80 63.75,80 66.25,80 68.75,80 71.25,80 73.75,80 76.25,80 78.75,80 81.25,80 83.75,80 86.25,80 88.75,80 91.25,80 93.75,80 96.25,80 98.75,80 103.75,80 108.75,80 111.25,80 113.75,80 116.25,80 118.75,80 123.75,80 126.25,80 128.75,80 2.5,82.5 7.5,82.5 25,82.5 27.5,82.5 32.5,82.5 35,82.5 37.5,82.5 40,82.5 42.5,82.5 45,82.5 47.5,82.5 50,82.5 52.5,82.5 107.5,82.5 110,82.5 112.5,82.5 115,82.5 117.5,82.5 23.925,83.4 8.75,85 31.25,85 38.75,85 41.25,85 43.75,85 46.25,85 48.75,85 51.25,85 53.75,85 56.25,85 58.75,85 61.25,85 63.75,85 66.25,85 68.75,85 71.25,85 73.75,85 76.25,85 78.75,85 81.25,85 83.75,85 86.25,85 88.75,85 91.25,85 98.75,85 101.25,85 103.75,85 106.25,85 108.75,85 111.25,85 113.75,85 116.25,85 118.75,85 121.25,85 128.75,85 25,87.5 27.5,87.5 32.5,87.5 37.5,87.5 40,87.5 42.5,87.5 45,87.5 47.5,87.5 50,87.5 52.5,87.5 62.5,87.5 72.5,87.5 75,87.5 77.5,87.5 80,87.5 82.5,87.5 85,87.5 87.5,87.5 90,87.5 92.5,87.5 97.5,87.5 100,87.5 102.5,87.5 105,87.5 107.5,87.5 110,87.5 112.5,87.5 115,87.5 117.5,87.5 120,87.5
  other v2: 113.47,30.83 112.82,31.08 114.12,31.08 112.82,34.28 114.12,34.28 113.47,34.53 90.24,35.97 90.94,35.97 91.64,35.97 92.34,35.97 93.04,35.97 89.89,36.67 90.59,36.67 91.29,36.67 91.99,36.67 92.69,36.67 93.39,36.67 90.24,37.37 90.94,37.37 91.64,37.37 92.34,37.37 93.04,37.37 11.434,43.684 12.45,43.684 13.466,43.684 11.434,44.7 12.45,44.7 13.466,44.7 11.434,45.716 12.45,45.716 13.466,45.716
  other v3: 68.6,24
  other v4: 25.5,46.45 26.6,46.45 27.7,46.45 25.5,47.55 26.6,47.55 27.7,47.55
GPIO_LED_A: R18.2 U4.61 | length 13.6
  Top Layer w0.15: R18.2@22.251,14.701 22.631,15.081 22.681,15.081 30.575,22.975 32.32,22.975 32.346,23 U4.61@32.385,23.039
GPIO_LED_B: R17.2 U4.60 | length 13
  Top Layer w0.15: R17.2@22.251,16.7 22.631,17.081 22.681,17.081 29.147,23.547 U4.60@32.385,23.547
GPIO_LED_C: R16.2 U4.59 | length 12.4
  Top Layer w0.15: R16.2@22.251,18.701 R16.2@22.631,19.081 ; R16.2@22.632,19.081 27.607,24.055 U4.59@32.33,24.055 ; U4.59@32.33,24 U4.59@32.385,24.055
GPIO_LED_D: R15.2 U4.58 | length 11.8
  Top Layer w0.15: R15.2@21.951,20.7 R15.2@21.989,20.738 ; R15.2@22.251,20.7 R15.2@22.289,20.738 ; R15.2@22.251,20.7 26.088,24.538 U4.58@32.385,24.538
IN_N: C61.1 U3.6 | length 31.4
  Top Layer w0.175: U3.6@66.55,22.55 66.55,22.369 cw(c66.443,22.369) 66.519,22.294 ccw(c66.642,22.169) 66.479,22.234 66.421,22.088 cw(c66.2,22.175) 66.348,21.989 ccw(c66.456,21.852) 66.281,21.852 66.265,17.003 66.265,13.138 ccw(c68.805,13.138) 67.008,11.342 69.562,8.788 ccw(c71.358,10.585) 71.358,8.045 84.851,8.045 ccw(c84.851,8.232) 84.984,8.1 ccw(c84.869,8.214) 85.031,8.214 cw(c85.193,8.214) 85.079,8.329 85.249,8.499 cw(c85.324,8.423) C61.1@85.324,8.53 ; C61.1@85.314,8.406 cw(c85.349,8.406) C61.1@85.324,8.43
  Top Layer w0.3: C61.1@85.314,8.406 cw(c85.349,8.406) C61.1@85.324,8.43
IN_P: C52.1 U3.4 | length 32
  Top Layer w0.175: U3.4@65.55,22.55 65.55,22.369 ccw(c65.657,22.369) 65.581,22.294 ccw(c65.657,22.369) 65.657,22.262 65.66,22.262 65.662,22.262 65.662,22.175 ccw(c65.9,22.175) 65.753,21.989 cw(c65.644,21.852) 65.819,21.851 65.835,17.001 65.835,16.572 65.836,13.136 ccw(c68.801,13.136) 66.704,11.039 69.259,8.484 ccw(c71.356,10.581) 71.356,7.615 84.851,7.615 cw(c84.851,7.428) 84.984,7.56 cw(c84.869,7.446) 85.031,7.446 ccw(c85.193,7.446) 85.079,7.331 85.249,7.161 ccw(c85.324,7.237) C52.1@85.324,7.13
  Top Layer w0.3: C52.1@85.374,7.13 ccw(c85.35,7.154) C52.1@85.384,7.154
LF_CEXT: C10.1 R7.1 TP8.1 U3.45 | length 16.6
  Top Layer w0.15: C10.1@52.906,21.6 52.907,21.599 R7.1@54.45,21.599 54.4,21.549 TP8.1@54.4,19.2 ; R7.1@54.45,21.599 55.752,22.899 55.752,24.352 57.35,25.95 60.15,25.95 61.9,24.2 62.342,24.2 62.692,24.55 U3.45@63.55,24.55
LP_FILTER_IN: C85.2 T3.8 | length 2
  Top Layer w0.199: C85.2@110.266,32.7 ccw(c110.314,32.748) 110.314,32.68 T3.8@112.295,32.68
MOSI: TP27.1 U4.27 U7.7 U8.7 U9.7 | length 81.6
  Top Layer w0.15: U4.27@43.815,26.545 43.88,26.609 44.609,26.609 45,27 v1(45.7,27) ; v2(50.95,33.05) 51.95,33.05 TP27.1@53.3,34.4 TP27.1@53.25,34.4 ; v1(84.658,16.652) 84.78,16.652 85.009,16.881 U9.7@85.525,16.881 ; v1(85.3,22) 91.98,22 93.1,20.88 U8.7@93.875,20.88 ; v1(101.3,18.9) 101.3,18.898 101.67,18.528 101.67,18.135 U7.7@101.72,18.085
  Bottom Layer w0.15: v1(45.7,27) 45.7,27.8 v2(50.95,33.05) 52.7,34.8 76.3,34.8 85.3,25.8 v1(85.3,22) ; v1(84.658,16.652) 85.306,17.3 v1@85.306,22 ; v1@93,20.9 99.3,20.9 v1(101.3,18.9)
  other v1: 93.1,20.9
NetC1_2: C1.2 FB1.1 P1.1 R1.1 | length 9.8
  Top Layer w0.2: P1.1@4.977,40.883 4.996,40.902 6.286,40.902 6.288,40.9 6.632,40.9 ; C1.2@6.7,45.448 6.7,40.968 6.632,40.9 ; FB1.1@8.539,42.492 8.471,42.424 8.471,41.006 R1.1@8.115,40.651 7.849,40.651 7.6,40.9 6.632,40.9
NetC2_2: C2.2 P1.2 R3.1 TP5.1 | length 28.6
  Top Layer w0.4: P1.2@4.977,40.233 6.753,40.233 6.826,40.16 v2(6.88,40.16) ; v2(10.4,38.9) 11.5,37.8 17.229,37.8 18.7,39.271 18.7,43.378 20.106,44.784 20.106,46.307 R3.1@19.301,47.111 ; C2.2@16.9,46.674 18.861,46.674 R3.1@19.3,47.111 TP5.1@19.3,49
  Bottom Layer w0.4: v2(6.88,40.16) 8.14,38.9 v2(10.4,38.9)
NetC3_2: C3.2 P1.3 R4.1 TP6.1 | length 16.7
  Top Layer w0.2: P1.3@4.977,39.583 4.997,39.563 7.264,39.563 7.648,39.946 11.278,39.946 11.931,40.6 13.9,40.6 ; TP6.1@13.3,39.1 13.3,40 13.9,40.6 ; C3.2@17.1,40.6 13.9,40.6
  Top Layer w0.4: C3.2@17.1,40.6 R4.1@17.1,42.949
NetC4_2: C4.2 C5.2 FB1.2 IC1.7 IC1.8 TP7.1 | length 25.2
  Top Layer w0.2: C5.2@13.3,49.674 13.3,49.698 14.44,50.838 14.44,51.34 15.35,52.25 15.55,52.25 ; IC1.8@13.95,47.05 14.488,47.05 ; IC1.7@14.8,46.2 14.776,46.2 14.726,46.25 14.726,46.812 14.488,47.05 ; TP7.1@16.8,53.5 15.55,52.25 ; 14.488,47.05 16.317,48.879 16.646,48.879 17.707,49.94 17.707,51.871 17.328,52.25 15.55,52.25
  Top Layer w0.5: FB1.2@8.539,43.4 8.6,43.4 8.6,47.15 11.1,49.65 C4.2@11.1,49.674 C5.2@13.3,49.674
NetC6_2: C6.2 R5.1 SW1.1 SW1.2 U4.37 | length 97.5
  Top Layer w0.15: U4.37@39.853,31.015 39.853,37.958 42.394,40.5 49.951,40.5 R5.1@50.1,40.351 50.298,40.549 60.224,40.549 66.776,47.1 96.8,47.1 101.826,52.126 C6.2@116.8,52.126 116.824,52.15 SW1.2@119.925,52.15 SW1.1@119.925,47.65
NetC7_2: C7.2 R6.1 SW2.1 SW2.2 U4.38 | length 100.5
  Top Layer w0.15: U4.38@39.345,31.015 39.345,37.874 42.37,40.9 46.895,40.9 R6.1@47.198,41.202 47.344,41.056 60.308,41.056 66.907,47.656 96.605,47.656 107.295,58.346 116.096,58.346 116.5,58.75 C7.2@116.5,58.774 116.524,58.75 SW2.1@119.725,58.75 SW2.2@119.725,63.25
NetC8_1: C8.1 U2.3 | length 4.6
  Top Layer w0.3: C8.1@61.4,38.826 61.4,38.802 61.729,38.473 61.753,38.473 62.726,37.5 U2.3@65.45,37.5
NetC9_1: C9.1 R7.2 | length 1.5
  Top Layer w0.15: C9.1@52.906,23.1 54.449,23.1 R7.2@54.45,23.101
NetC11_3: C11.3 FB3.1 FB4.1 | length 2.9
  Top Layer w0.5: FB4.1@69.37,18.716 FB3.1@72.221,18.716
NetC12_1: C12.1 R8.1 X1.1 | length 4
  Top Layer w0.15: C12.1@63.325,34.099 C12.1@63.35,34.124 ; X1.1@65.226,34.124 X1.1@65.3,34.05
  Top Layer w0.3: R8.1@61.35,34.099 C12.1@63.325,34.099 ; C12.1@63.35,34.124 X1.1@65.226,34.124
NetC13_1: C13.1 R9.2 X1.3 | length 4
  Top Layer w0.3: X1.3@67.5,35.65 67.574,35.576 C13.1@69.45,35.576 69.475,35.601 R9.2@71.45,35.601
